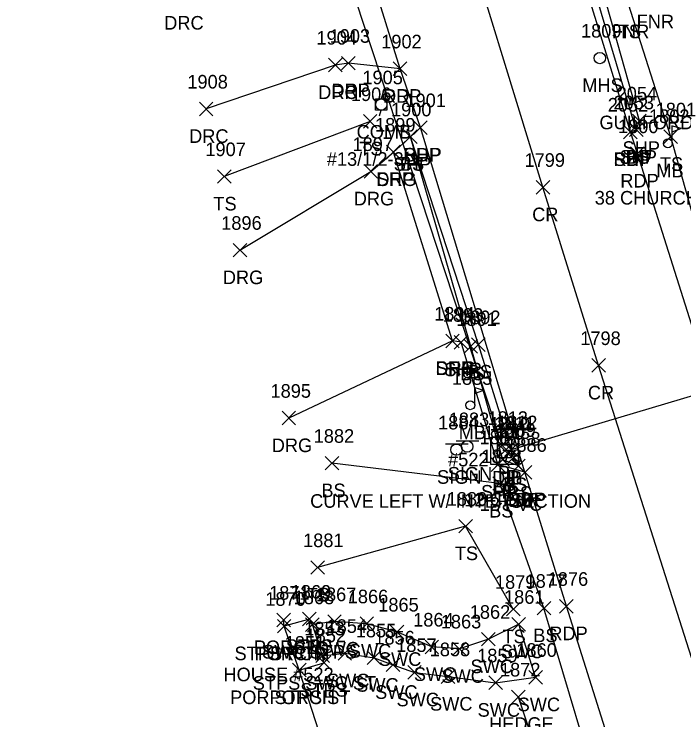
# Model space of a CAD drawing. Extents: x 1620157 to 1620595, y 115111 to 117885.
# Drawn here: x 1620193.4 to 1620291.9, y 115548.1 to 115651.9 of the extents above; entities that cross this region are included whole.
import ezdxf

# ---------------------------------------------------------------- set-up
doc = ezdxf.new("R2010")
doc.units = 0
for name, color, linetype in [('D_A', 7, 'Continuous'), ('D_C', 7, 'Continuous'), ('D_I', 7, 'Continuous'), ('D_TIC', 7, 'Continuous'), ('DCP', 7, 'Continuous'), ('DS', 7, 'Continuous'), ('L_A', 7, 'Continuous'), ('L_C', 7, 'Continuous'), ('L_I', 7, 'Continuous'), ('L_TIC', 7, 'Continuous'), ('LAHR', 7, 'Continuous'), ('LBF', 7, 'Continuous'), ('LELB', 7, 'Continuous'), ('LMB', 7, 'Continuous'), ('P_A', 7, 'Continuous'), ('P_I', 7, 'Continuous'), ('P_TIC', 7, 'Continuous'), ('PET', 7, 'Continuous'), ('PRC', 7, 'Continuous'), ('PSP', 7, 'Continuous'), ('R_A', 7, 'Continuous'), ('R_I', 7, 'Continuous'), ('R_TIC', 7, 'Continuous'), ('RDG', 7, 'Continuous'), ('RDP', 7, 'Continuous'), ('RSW', 7, 'Continuous'), ('S_A', 7, 'Continuous'), ('S_C', 7, 'Continuous'), ('S_I', 7, 'Continuous'), ('SSGN', 7, 'Continuous'), ('U_A', 7, 'Continuous'), ('U_C', 7, 'Continuous'), ('U_I', 7, 'Continuous'), ('UP', 7, 'Continuous'), ('USMH', 7, 'Continuous')]:
    doc.layers.add(name, color=color, linetype=linetype)

msp = doc.modelspace()

# ---------------------------------------------------------------- linework, layer by layer
at = {"layer": 'D_TIC'}
for points in [[(1620264.11, 115587.48), (1620266.11, 115589.48)], [(1620266.11, 115587.48), (1620264.11, 115589.48)], [(1620264.55, 115586.7), (1620266.55, 115588.7)], [(1620266.55, 115586.7), (1620264.55, 115588.7)], [(1620265.48, 115586.84), (1620267.48, 115588.84)], [(1620267.48, 115586.84), (1620265.48, 115588.84)]]:
    msp.add_lwpolyline(points, dxfattribs=at)
at = {"layer": 'DCP'}
for points in [[(1620265.11, 115588.48), (1620223.38, 115715.62)], [(1620298.2, 115597.27), (1620266.48, 115587.84)]]:
    msp.add_lwpolyline(points, dxfattribs=at)
at = {"layer": 'DS'}
for p, q in [((1620263.47, 115589.66), (1620267.47, 115589.66)), ((1620263.47, 115585.66), (1620263.47, 115589.66)), ((1620267.47, 115589.66), (1620267.47, 115585.66)), ((1620264.47, 115586.66), (1620264.47, 115588.66)), ((1620264.47, 115588.66), (1620266.47, 115588.66)), ((1620266.47, 115588.66), (1620266.47, 115586.66)), ((1620265.48, 115587.66), (1620265.48, 115587.66)), ((1620265.48, 115587.66), (1620265.48, 115587.66)), ((1620266.47, 115586.66), (1620264.47, 115586.66)), ((1620267.47, 115585.66), (1620263.47, 115585.66))]:
    msp.add_line(p, q, dxfattribs=at)
at = {"layer": 'L_TIC'}
for points in [[(1620244.72, 115635.13), (1620246.72, 115637.13)], [(1620246.72, 115635.13), (1620244.72, 115637.13)], [(1620283.85, 115633.91), (1620285.85, 115635.91)], [(1620285.85, 115633.91), (1620283.85, 115635.91)], [(1620250.64, 115632.88), (1620252.64, 115634.88)], [(1620252.64, 115632.88), (1620250.64, 115634.88)], [(1620250.64, 115632.88), (1620252.64, 115634.88)], [(1620252.64, 115632.88), (1620250.64, 115634.88)], [(1620288.92, 115632.87), (1620290.92, 115634.87)], [(1620290.92, 115632.87), (1620288.92, 115634.87)], [(1620223.26, 115627.03), (1620225.26, 115629.03)], [(1620225.26, 115627.03), (1620223.26, 115629.03)], [(1620260.63, 115602.3), (1620262.63, 115604.3)], [(1620262.63, 115602.3), (1620260.63, 115604.3)], [(1620259.53, 115602.04), (1620261.53, 115604.04)], [(1620261.53, 115602.04), (1620259.53, 115604.04)], [(1620265.82, 115585.73), (1620267.82, 115587.73)], [(1620267.82, 115585.73), (1620265.82, 115587.73)], [(1620239.11, 115584.85), (1620241.11, 115586.85)], [(1620241.11, 115584.85), (1620239.11, 115586.85)], [(1620264.21, 115585.36), (1620266.21, 115587.36)], [(1620266.21, 115585.36), (1620264.21, 115587.36)], [(1620266.53, 115584.45), (1620268.53, 115586.45)], [(1620268.53, 115584.45), (1620266.53, 115586.45)], [(1620266.53, 115584.45), (1620268.53, 115586.45)], [(1620268.53, 115584.45), (1620266.53, 115586.45)], [(1620263.78, 115581.86), (1620265.78, 115583.86)], [(1620265.78, 115581.86), (1620263.78, 115583.86)], [(1620258.76, 115575.59), (1620260.76, 115577.59)], [(1620260.76, 115575.59), (1620258.76, 115577.59)], [(1620236.99, 115569.5), (1620238.99, 115571.5)], [(1620238.99, 115569.5), (1620236.99, 115571.5)], [(1620265.77, 115563.37), (1620267.77, 115565.37)], [(1620267.77, 115563.37), (1620265.77, 115565.37)], [(1620270.27, 115563.52), (1620272.27, 115565.52)], [(1620272.27, 115563.52), (1620270.27, 115565.52)], [(1620231.99, 115561.77), (1620233.99, 115563.77)], [(1620233.99, 115561.77), (1620231.99, 115563.77)], [(1620235.79, 115561.92), (1620237.79, 115563.92)], [(1620237.79, 115561.92), (1620235.79, 115563.92)], [(1620232.08, 115560.87), (1620234.08, 115562.87)], [(1620234.08, 115560.87), (1620232.08, 115562.87)], [(1620232.08, 115560.87), (1620234.08, 115562.87)], [(1620234.08, 115560.87), (1620232.08, 115562.87)], [(1620236.22, 115561.11), (1620238.22, 115563.11)], [(1620238.22, 115561.11), (1620236.22, 115563.11)], [(1620237.72, 115556.52), (1620239.72, 115558.52)], [(1620239.72, 115556.52), (1620237.72, 115558.52)], [(1620237.93, 115555.5), (1620239.93, 115557.5)], [(1620239.93, 115555.5), (1620237.93, 115557.5)], [(1620234.29, 115554.41), (1620236.29, 115556.41)], [(1620236.29, 115554.41), (1620234.29, 115556.41)], [(1620234.29, 115554.41), (1620236.29, 115556.41)], [(1620236.29, 115554.41), (1620234.29, 115556.41)], [(1620266.51, 115550.47), (1620268.51, 115552.47)], [(1620268.51, 115550.47), (1620266.51, 115552.47)]]:
    msp.add_lwpolyline(points, dxfattribs=at)
at = {"layer": 'LAHR'}
msp.add_lwpolyline([(1620267.51, 115551.47), (1620274.04, 115531.66)], dxfattribs=at)
at = {"layer": 'LBF'}
for points in [[(1620241.04, 115537.59), (1620235.29, 115555.41), (1620233.08, 115561.87), (1620232.99, 115562.77)], [(1620235.29, 115555.41), (1620238.93, 115556.5), (1620238.72, 115557.52), (1620237.22, 115562.11), (1620236.79, 115562.92), (1620233.08, 115561.87)]]:
    msp.add_lwpolyline(points, dxfattribs=at)
at = {"layer": 'LELB'}
for points in [[(1620284.85, 115634.91), (1620272.28, 115677.07), (1620264.79, 115700.58)], [(1620299.44, 115600.05), (1620289.92, 115633.87), (1620283.73, 115653.38)], [(1620245.72, 115636.13), (1620224.26, 115628.03)], [(1620267.53, 115585.45), (1620266.82, 115586.73), (1620261.63, 115603.3), (1620251.64, 115633.88)], [(1620267.53, 115585.45), (1620265.21, 115586.36), (1620260.53, 115603.04), (1620251.64, 115633.88)], [(1620264.24, 115517.48), (1620278.78, 115521.68), (1620281.32, 115522.21), (1620280.6, 115533.12), (1620271.27, 115564.52), (1620264.78, 115582.86), (1620240.11, 115585.85)], [(1620266.77, 115564.37), (1620259.76, 115576.59), (1620237.99, 115570.5)]]:
    msp.add_lwpolyline(points, dxfattribs=at)
at = {"layer": 'LMB'}
for p, q in [((1620290.15, 115632.91), (1620290.15, 115635.51)), ((1620290.15, 115635.5), (1620291.44, 115635.12)), ((1620290.15, 115634.6), (1620291.43, 115635.11)), ((1620289.5, 115632.9), (1620289.5, 115632.9)), ((1620261.09, 115596.98), (1620262.38, 115596.6)), ((1620261.09, 115594.39), (1620261.09, 115596.98)), ((1620261.09, 115596.08), (1620262.37, 115596.59)), ((1620260.44, 115594.38), (1620260.44, 115594.38))]:
    msp.add_line(p, q, dxfattribs=at)
for centre in [(1620289.5, 115632.9), (1620260.44, 115594.38)]:
    msp.add_circle(centre, 0.656, dxfattribs=at)
at = {"layer": 'P_TIC'}
for points in [[(1620249.12, 115642.88), (1620251.12, 115644.88)], [(1620251.12, 115642.88), (1620249.12, 115644.88)], [(1620284.31, 115635.21), (1620286.31, 115637.21)], [(1620286.31, 115635.21), (1620284.31, 115637.21)], [(1620252.11, 115634.23), (1620254.11, 115636.23)], [(1620254.11, 115634.23), (1620252.11, 115636.23)], [(1620252.11, 115634.23), (1620254.11, 115636.23)], [(1620254.11, 115634.23), (1620252.11, 115636.23)], [(1620283, 115633.58), (1620285, 115635.58)], [(1620285, 115633.58), (1620283, 115635.58)], [(1620283, 115633.58), (1620285, 115635.58)], [(1620285, 115633.58), (1620283, 115635.58)], [(1620283.85, 115633.91), (1620285.85, 115635.91)], [(1620285.85, 115633.91), (1620283.85, 115635.91)], [(1620250.64, 115632.88), (1620252.64, 115634.88)], [(1620252.64, 115632.88), (1620250.64, 115634.88)], [(1620248.14, 115630.63), (1620250.14, 115632.63)], [(1620250.14, 115630.63), (1620248.14, 115632.63)], [(1620284.02, 115630.41), (1620286.02, 115632.41)], [(1620286.02, 115630.41), (1620284.02, 115632.41)], [(1620270.12, 115625.45), (1620272.12, 115627.45)], [(1620272.12, 115625.45), (1620270.12, 115627.45)], [(1620256.83, 115602.83), (1620258.83, 115604.83)], [(1620258.83, 115602.83), (1620256.83, 115604.83)], [(1620258.09, 115602.65), (1620260.09, 115604.65)], [(1620260.09, 115602.65), (1620258.09, 115604.65)], [(1620278.31, 115599.23), (1620280.31, 115601.23)], [(1620280.31, 115599.23), (1620278.31, 115601.23)], [(1620263.5, 115584.64), (1620265.5, 115586.64)], [(1620265.5, 115584.64), (1620263.5, 115586.64)], [(1620267.48, 115583.52), (1620269.48, 115585.52)], [(1620269.48, 115583.52), (1620267.48, 115585.52)], [(1620267.48, 115583.52), (1620269.48, 115585.52)], [(1620269.48, 115583.52), (1620267.48, 115585.52)], [(1620273.58, 115563.81), (1620275.58, 115565.81)], [(1620275.58, 115563.81), (1620273.58, 115565.81)]]:
    msp.add_lwpolyline(points, dxfattribs=at)
at = {"layer": 'PET'}
for points in [[(1620336.22, 115456.8), (1620332.52, 115469.32), (1620324.59, 115500.95), (1620318.09, 115527.23), (1620313.06, 115541.76), (1620309.74, 115554.43), (1620302.9, 115574.33), (1620297.63, 115590.44), (1620296.31, 115595.42), (1620295.45, 115598.55), (1620285.02, 115631.41), (1620284, 115634.58), (1620271.05, 115676.55), (1620263.94, 115701.46), (1620257.2, 115724.05), (1620247.86, 115755.87), (1620237.56, 115791.5), (1620229.87, 115820.37), (1620222.52, 115845.46)], [(1620320.14, 115439.39), (1620314.87, 115455.06), (1620309.06, 115464.39), (1620304.22, 115479.4), (1620297.09, 115496.09), (1620293.95, 115506.93), (1620292.02, 115512.47), (1620283.67, 115536.02), (1620274.58, 115564.81), (1620268.48, 115584.52), (1620253.11, 115635.23), (1620250.12, 115643.88), (1620242.65, 115668.01), (1620237.66, 115684.19), (1620235.08, 115693.76), (1620231.19, 115707.41), (1620225.41, 115727.43), (1620211.93, 115771.95), (1620203.83, 115799.04), (1620193.37, 115837.22)]]:
    msp.add_lwpolyline(points, dxfattribs=at)
at = {"layer": 'PRC'}
msp.add_lwpolyline([(1620328.08, 115447.46), (1620322.14, 115466.61), (1620311.32, 115499.81), (1620303.78, 115522.91), (1620294.72, 115551.74), (1620279.31, 115600.23), (1620271.12, 115626.45), (1620257.91, 115669.49), (1620247.64, 115703.03), (1620242.45, 115719.65), (1620232.98, 115752.35), (1620223.66, 115784.04), (1620214.14, 115816.15), (1620207.47, 115841.18)], dxfattribs=at)
at = {"layer": 'PSP'}
for points in [[(1620284, 115634.58), (1620284.85, 115634.91), (1620285.31, 115636.21), (1620274.47, 115674.84), (1620275.53, 115678.07), (1620276.55, 115679.8), (1620271.76, 115697.36), (1620266.72, 115698.51), (1620264.79, 115700.58), (1620263.94, 115701.46)], [(1620268.48, 115584.52), (1620264.5, 115585.64), (1620259.09, 115603.65), (1620257.83, 115603.83), (1620249.14, 115631.63), (1620251.64, 115633.88), (1620253.11, 115635.23)]]:
    msp.add_lwpolyline(points, dxfattribs=at)
at = {"layer": 'R_TIC'}
for points in [[(1620241.53, 115643.7), (1620243.53, 115645.7)], [(1620243.53, 115643.7), (1620241.53, 115645.7)], [(1620239.59, 115643.43), (1620241.59, 115645.43)], [(1620241.59, 115643.43), (1620239.59, 115645.43)], [(1620239.59, 115643.43), (1620241.59, 115645.43)], [(1620241.59, 115643.43), (1620239.59, 115645.43)], [(1620249.12, 115642.88), (1620251.12, 115644.88)], [(1620251.12, 115642.88), (1620249.12, 115644.88)], [(1620220.61, 115636.97), (1620222.61, 115638.97)], [(1620222.61, 115636.97), (1620220.61, 115638.97)], [(1620248.14, 115630.63), (1620250.14, 115632.63)], [(1620250.14, 115630.63), (1620248.14, 115632.63)], [(1620244.82, 115627.78), (1620246.82, 115629.78)], [(1620246.82, 115627.78), (1620244.82, 115629.78)], [(1620225.57, 115616.19), (1620227.57, 115618.19)], [(1620227.57, 115616.19), (1620225.57, 115618.19)], [(1620256.83, 115602.83), (1620258.83, 115604.83)], [(1620258.83, 115602.83), (1620256.83, 115604.83)], [(1620232.76, 115591.48), (1620234.76, 115593.48)], [(1620234.76, 115591.48), (1620232.76, 115593.48)], [(1620236.22, 115561.11), (1620238.22, 115563.11)], [(1620238.22, 115561.11), (1620236.22, 115563.11)], [(1620239.48, 115561.55), (1620241.48, 115563.55)], [(1620241.48, 115561.55), (1620239.48, 115563.55)], [(1620244.23, 115561.24), (1620246.23, 115563.24)], [(1620246.23, 115561.24), (1620244.23, 115563.24)], [(1620266.58, 115561.16), (1620268.58, 115563.16)], [(1620268.58, 115561.16), (1620266.58, 115563.16)], [(1620248.65, 115560.03), (1620250.65, 115562.03)], [(1620250.65, 115560.03), (1620248.65, 115562.03)], [(1620262.11, 115558.96), (1620264.11, 115560.96)], [(1620264.11, 115558.96), (1620262.11, 115560.96)], [(1620253.79, 115557.82), (1620255.79, 115559.82)], [(1620255.79, 115557.82), (1620253.79, 115559.82)], [(1620257.85, 115557.54), (1620259.85, 115559.54)], [(1620259.85, 115557.54), (1620257.85, 115559.54)], [(1620237.72, 115556.52), (1620239.72, 115558.52)], [(1620239.72, 115556.52), (1620237.72, 115558.52)], [(1620241, 115556.88), (1620243, 115558.88)], [(1620243, 115556.88), (1620241, 115558.88)], [(1620245.3, 115556.23), (1620247.3, 115558.23)], [(1620247.3, 115556.23), (1620245.3, 115558.23)], [(1620248.08, 115555.18), (1620250.08, 115557.18)], [(1620250.08, 115555.18), (1620248.08, 115557.18)], [(1620251.24, 115554.08), (1620253.24, 115556.08)], [(1620253.24, 115554.08), (1620251.24, 115556.08)], [(1620256.17, 115553.45), (1620258.17, 115555.45)], [(1620258.17, 115553.45), (1620256.17, 115555.45)], [(1620269.05, 115553.36), (1620271.05, 115555.36)], [(1620271.05, 115553.36), (1620269.05, 115555.36)], [(1620263.16, 115552.55), (1620265.16, 115554.55)], [(1620265.16, 115552.55), (1620263.16, 115554.55)]]:
    msp.add_lwpolyline(points, dxfattribs=at)
at = {"layer": 'RDG'}
for points in [[(1620226.57, 115617.19), (1620245.82, 115628.78), (1620249.14, 115631.63)], [(1620257.83, 115603.83), (1620233.76, 115592.48)]]:
    msp.add_lwpolyline(points, dxfattribs=at)
at = {"layer": 'RDP'}
for points in [[(1620250.12, 115643.88), (1620242.53, 115644.7), (1620240.59, 115644.43)], [(1620240.59, 115644.43), (1620221.61, 115637.97)]]:
    msp.add_lwpolyline(points, dxfattribs=at)
at = {"layer": 'RSW'}
msp.add_lwpolyline([(1620238.72, 115557.52), (1620242, 115557.88), (1620246.3, 115557.23), (1620249.08, 115556.18), (1620252.24, 115555.08), (1620257.17, 115554.45), (1620264.16, 115553.55), (1620270.05, 115554.36), (1620267.58, 115562.16), (1620263.11, 115559.96), (1620258.85, 115558.54), (1620254.79, 115558.82), (1620249.65, 115561.03), (1620245.23, 115562.24), (1620240.48, 115562.55), (1620237.22, 115562.11)], dxfattribs=at)
at = {"layer": 'SSGN'}
for p, q in [((1620256.78, 115588.68), (1620260.11, 115588.68)), ((1620258.35, 115589.14), (1620261.68, 115589.14)), ((1620258.42, 115587.84), (1620258.42, 115587.84)), ((1620259.99, 115588.31), (1620259.99, 115588.31))]:
    msp.add_line(p, q, dxfattribs=at)
for centre in [(1620258.42, 115587.84), (1620259.99, 115588.31)]:
    msp.add_circle(centre, 0.833, dxfattribs=at)
at = {"layer": 'UP'}
for p, q in [((1620246.51, 115637.77), (1620246.51, 115639.44)), ((1620246.51, 115639.44), (1620248.18, 115639.44)), ((1620247.6, 115640.27), (1620247.35, 115639.44)), ((1620248.18, 115639.44), (1620248.18, 115637.77)), ((1620247.35, 115638.6), (1620247.35, 115638.6)), ((1620248.18, 115637.77), (1620246.51, 115637.77)), ((1620247.1, 115636.94), (1620247.35, 115637.77))]:
    msp.add_line(p, q, dxfattribs=at)
msp.add_circle((1620247.35, 115638.6), 0.833, dxfattribs=at)
at = {"layer": 'USMH'}
for p, q in [((1620279.5, 115645.46), (1620279.5, 115645.46)), ((1620280.34, 115645.46), (1620280.34, 115645.46))]:
    msp.add_line(p, q, dxfattribs=at)
msp.add_circle((1620279.5, 115645.46), 0.833, dxfattribs=at)

# ---------------------------------------------------------------- texts
at = {"layer": 'D_A'}
for s, p in [('P', (1620264.48, 115583.48)), ('DIB', (1620263.65, 115582.7)), ('DI', (1620264.54, 115582.66)), ('P', (1620265.86, 115582.84))]:
    msp.add_text(s, height=2, dxfattribs=at).set_placement(p)
at = {"layer": 'D_C'}
for s, p in [('12 CPEP', (1620259.57, 115579.48)), ('12 PVC', (1620261.82, 115578.84))]:
    msp.add_text(s, height=2, dxfattribs=at).set_placement(p)
at = {"layer": 'D_I'}
for s, p in [('1813', (1620262.98, 115591.48)), ('1811', (1620263.99, 115590.7)), ('1812', (1620264.36, 115590.84)), ('1810', (1620263.27, 115590.66))]:
    msp.add_text(s, height=2, dxfattribs=at).set_placement(p)
at = {"layer": 'L_A'}
for s, p in [('FNR', (1620284.91, 115649.84)), ('FNR', (1620281.27, 115648.38)), ('TS', (1620282.14, 115648.38)), ('TS', (1620244.13, 115631.13)), ('BS', (1620283.29, 115629.91)), ('BS', (1620250.09, 115628.88)), ('BS', (1620250.09, 115628.88)), ('TS', (1620288.33, 115628.87)), ('MB', (1620287.8, 115627.9)), ('TS', (1620222.67, 115623.03)), ('BS', (1620258.97, 115598.04)), ('BS', (1620260.07, 115598.3)), ('MB', (1620258.74, 115589.38)), ('BS', (1620263.65, 115581.36)), ('BS', (1620265.26, 115581.73)), ('BS', (1620238.55, 115580.85)), ('BS', (1620265.97, 115580.45)), ('BS', (1620265.97, 115580.45)), ('BS', (1620263.22, 115577.86)), ('TS', (1620258.17, 115571.59)), ('TS', (1620236.4, 115565.5)), ('TS', (1620265.18, 115559.37)), ('BS', (1620269.71, 115559.52)), ('PORCH', (1620228.61, 115557.77)), ('STPS', (1620233.31, 115557.92)), ('STPS POR', (1620225.78, 115556.87)), ('PORCH', (1620228.7, 115556.87)), ('SWC STPS', (1620229.83, 115557.11)), ('STPS SWC ST', (1620228.46, 115552.52)), ('STPS', (1620235.45, 115551.5)), ('POR STPS ST', (1620225.13, 115550.41)), ('PORCH', (1620230.91, 115550.41)), ('HEDGE', (1620263.21, 115546.47))]:
    msp.add_text(s, height=2, dxfattribs=at).set_placement(p)
at = {"layer": 'L_C'}
for s, p in [('38 CHURCH DR', (1620278.75, 115623.9)), ('#522', (1620257.18, 115585.38)), ('HOUSE #522', (1620224.15, 115553.77))]:
    msp.add_text(s, height=2, dxfattribs=at).set_placement(p)
at = {"layer": 'L_I'}
for s, p in [('1906', (1620242.89, 115639.13)), ('2053', (1620281.51, 115637.91)), ('1900', (1620248.79, 115636.88)), ('1900', (1620248.79, 115636.88)), ('1801', (1620287.71, 115636.87)), ('1802', (1620286.72, 115635.9)), ('1907', (1620221.49, 115631.03)), ('1892', (1620258.94, 115606.3)), ('1891', (1620258.4, 115606.04)), ('1885', (1620257.74, 115597.38)), ('1889', (1620264.12, 115589.73)), ('1882', (1620237.42, 115588.85)), ('1890', (1620262.43, 115589.36)), ('1888', (1620264.83, 115588.45)), ('1888', (1620264.83, 115588.45)), ('1878', (1620262.08, 115585.86)), ('1880', (1620256.98, 115579.59)), ('1881', (1620235.86, 115573.5)), ('1879', (1620264.07, 115567.37)), ('1877', (1620268.57, 115567.52)), ('1871', (1620230.86, 115565.77)), ('1869', (1620234.04, 115565.92)), ('1870', (1620230.3, 115564.87)), ('1870', (1620230.3, 115564.87)), ('1868', (1620234.48, 115565.11)), ('1853', (1620236.03, 115560.52)), ('1852', (1620236.23, 115559.5)), ('1851', (1620233.16, 115558.41)), ('1851', (1620233.16, 115558.41)), ('1872', (1620264.81, 115554.47))]:
    msp.add_text(s, height=2, dxfattribs=at).set_placement(p)
at = {"layer": 'P_A'}
for s, p in [('RDP', (1620247.61, 115638.88)), ('SHP', (1620282.84, 115631.21)), ('SHP', (1620250.65, 115630.23)), ('RDP', (1620250.6, 115630.23)), ('SHP', (1620281.54, 115629.58)), ('RDP', (1620281.49, 115629.58)), ('SHP', (1620282.39, 115629.91)), ('SHP', (1620249.18, 115628.88)), ('SHP', (1620246.68, 115626.63)), ('RDP', (1620282.51, 115626.41)), ('CR', (1620269.55, 115621.45)), ('SHP', (1620255.36, 115598.83)), ('SHP', (1620256.62, 115598.65)), ('CR', (1620277.74, 115595.23)), ('SHP', (1620262.03, 115580.64)), ('SHP', (1620266.02, 115579.52)), ('RDP', (1620265.97, 115579.52)), ('RDP', (1620272.07, 115559.81))]:
    msp.add_text(s, height=2, dxfattribs=at).set_placement(p)
at = {"layer": 'P_I'}
for s, p in [('1902', (1620247.35, 115646.88)), ('2054', (1620281.97, 115639.21)), ('1901', (1620250.91, 115638.23)), ('1901', (1620250.91, 115638.23)), ('2052', (1620280.66, 115637.58)), ('2052', (1620280.66, 115637.58)), ('2053', (1620281.51, 115637.91)), ('1900', (1620248.79, 115636.88)), ('1899', (1620246.44, 115634.63)), ('1800', (1620282.17, 115634.41)), ('1799', (1620268.42, 115629.45)), ('1894', (1620255.13, 115606.83)), ('1893', (1620256.4, 115606.65)), ('1798', (1620276.62, 115603.23)), ('1887', (1620261.8, 115588.64)), ('1886', (1620265.74, 115587.52)), ('1886', (1620265.74, 115587.52)), ('1876', (1620271.83, 115567.81))]:
    msp.add_text(s, height=2, dxfattribs=at).set_placement(p)
at = {"layer": 'R_A'}
for s, p in [('DRC', (1620215.44, 115649.64)), ('DRP', (1620240.02, 115639.7)), ('DRC', (1620238.08, 115639.43)), ('DRP', (1620238.08, 115639.43)), ('DRP', (1620247.61, 115638.88)), ('DRC', (1620219.1, 115632.97)), ('DRG', (1620246.63, 115626.63)), ('DRG', (1620243.31, 115623.78)), ('DRG', (1620224.06, 115612.19)), ('DRG', (1620255.32, 115598.83)), ('DRG', (1620231.25, 115587.48)), ('SWC', (1620237.85, 115557.55)), ('SWC STPS', (1620229.83, 115557.11)), ('SWC', (1620242.59, 115557.24)), ('SWC', (1620264.94, 115557.16)), ('SWC', (1620247.01, 115556.03)), ('SWC', (1620260.48, 115554.96)), ('SWC', (1620252.15, 115553.82)), ('SWC', (1620256.21, 115553.54)), ('STPS SWC ST', (1620228.46, 115552.52)), ('SWC', (1620239.37, 115552.88)), ('SWC', (1620243.66, 115552.23)), ('SWC', (1620246.45, 115551.18)), ('SWC', (1620249.6, 115550.08)), ('SWC', (1620254.53, 115549.45)), ('SWC', (1620267.41, 115549.36)), ('SWC', (1620261.52, 115548.55))]:
    msp.add_text(s, height=2, dxfattribs=at).set_placement(p)
at = {"layer": 'R_I'}
for s, p in [('1904', (1620237.82, 115647.43)), ('1904', (1620237.82, 115647.43)), ('1903', (1620239.76, 115647.7)), ('1902', (1620247.35, 115646.88)), ('1908', (1620218.84, 115640.97)), ('1899', (1620246.44, 115634.63)), ('1897', (1620243.13, 115631.78)), ('1896', (1620223.82, 115620.19)), ('1894', (1620255.13, 115606.83)), ('1895', (1620231.07, 115595.48)), ('1868', (1620234.48, 115565.11)), ('1867', (1620237.74, 115565.55)), ('1866', (1620242.43, 115565.24)), ('1861', (1620265.41, 115565.16)), ('1865', (1620246.91, 115564.03)), ('1862', (1620260.37, 115562.96)), ('1864', (1620252.05, 115561.82)), ('1854', (1620239.31, 115560.88)), ('1863', (1620256.11, 115561.54)), ('1853', (1620236.03, 115560.52)), ('1855', (1620243.61, 115560.23)), ('1856', (1620246.33, 115559.18)), ('1857', (1620249.55, 115558.08)), ('1858', (1620254.48, 115557.45)), ('1859', (1620261.46, 115556.55)), ('1860', (1620267.22, 115557.36))]:
    msp.add_text(s, height=2, dxfattribs=at).set_placement(p)
at = {"layer": 'S_A'}
for p in [(1620255.56, 115582.82), (1620257.13, 115583.29)]:
    msp.add_text('SIGN', height=2, dxfattribs=at).set_placement(p)
at = {"layer": 'S_C'}
for s, p in [('GUILFORD COMMUNITY CHURCH', (1620279.44, 115634.98)), ('CURVE LEFT W/ INTERSECTION', (1620236.9, 115579.29))]:
    msp.add_text(s, height=2, dxfattribs=at).set_placement(p)
at = {"layer": 'S_I'}
for s, p in [('1884', (1620255.71, 115590.82)), ('1883', (1620257.28, 115591.29))]:
    msp.add_text(s, height=2, dxfattribs=at).set_placement(p)
at = {"layer": 'U_A'}
for s, p in [('MHS', (1620276.92, 115640.46)), ('COMB', (1620243.73, 115633.6))]:
    msp.add_text(s, height=2, dxfattribs=at).set_placement(p)
at = {"layer": 'U_C'}
msp.add_text('#13/1/2-3/1', height=2, dxfattribs=at).set_placement((1620239.35, 115629.6))
at = {"layer": 'U_I'}
for s, p in [('1809', (1620276.73, 115648.46)), ('1905', (1620244.58, 115641.6))]:
    msp.add_text(s, height=2, dxfattribs=at).set_placement(p)

doc.saveas('drawing.dxf')
